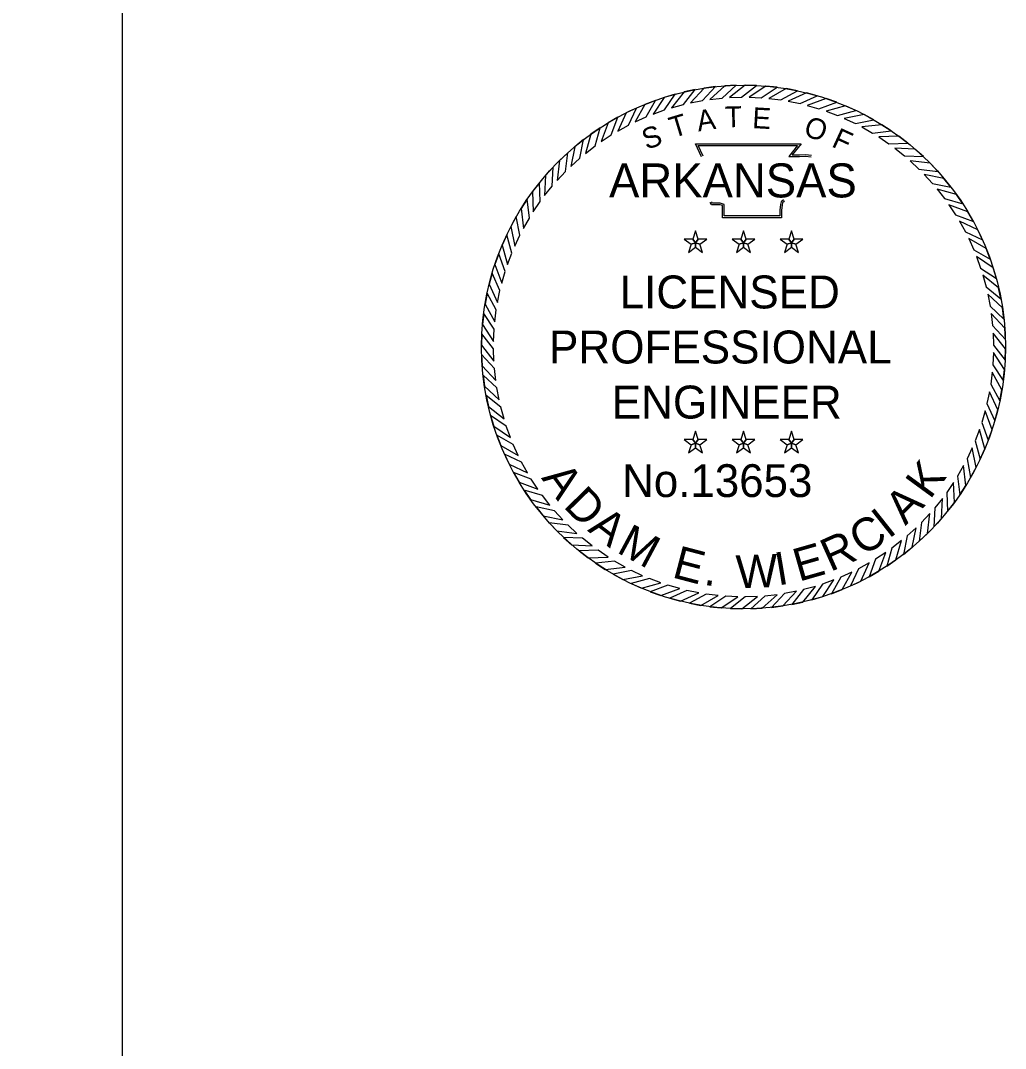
# Model space of a CAD drawing. Extents: x 0 to 38, y -1.3 to 22.5.
# Drawn here: x 33.533 to 38.045, y 10.605 to 15.315 of the extents above; entities that cross this region are included whole.
import ezdxf

# ---------------------------------------------------------------- set-up
doc = ezdxf.new("R2010")
doc.units = 0
for name, color, linetype in [('G-ANNO-STMP', 7, 'Continuous'), ('G-Border-Paper', 7, 'Continuous'), ('G-No Plot-Stamp-1', 7, 'Continuous'), ('G-No Plot-Stamp-2', 7, 'Continuous')]:
    doc.layers.add(name, color=color, linetype=linetype)

msp = doc.modelspace()

# ---------------------------------------------------------------- linework, layer by layer
at = {"layer": 'G-ANNO-STMP'}
for points in [[(36.623, 14.9987), (36.5725, 14.988), (36.5152, 14.9161), (36.569, 14.9308)], [(36.7162, 15.0124), (36.665, 15.0058), (36.6023, 14.9385), (36.657, 14.949)], [(36.8102, 15.0188), (36.7587, 15.0162), (36.6908, 14.9541), (36.7463, 14.9602)], [(36.9044, 15.0178), (36.8528, 15.0192), (36.7804, 14.9626), (36.8361, 14.9644)], [(36.9983, 15.0094), (36.947, 15.0149), (36.8703, 14.9641), (36.926, 14.9615)], [(37.0912, 14.9936), (37.0405, 15.0032), (36.96, 14.9586), (37.0153, 14.9516)], [(37.1826, 14.9707), (37.1327, 14.9841), (37.049, 14.946), (37.1036, 14.9347)], [(36.4412, 14.9495), (36.393, 14.9311), (36.3477, 14.851), (36.3985, 14.874)], [(36.5311, 14.9776), (36.4816, 14.9631), (36.4302, 14.8868), (36.4826, 14.9057)], [(37.2719, 14.9406), (37.2233, 14.9579), (37.1368, 14.9265), (37.1904, 14.9109)], [(36.3537, 14.9143), (36.3071, 14.8922), (36.2682, 14.8089), (36.3171, 14.8357)], [(37.3585, 14.9036), (37.3114, 14.9247), (37.2228, 14.9001), (37.275, 14.8804)], [(36.2693, 14.8725), (36.2246, 14.8468), (36.1924, 14.7606), (36.239, 14.7912)], [(37.442, 14.8599), (37.3967, 14.8847), (37.3064, 14.8671), (37.3569, 14.8434)], [(37.5218, 14.8098), (37.4786, 14.8381), (37.3872, 14.8276), (37.4357, 14.8)], [(36.1885, 14.8241), (36.1459, 14.795), (36.1205, 14.7065), (36.1646, 14.7407)], [(36.1116, 14.7695), (36.0715, 14.7371), (36.0531, 14.647), (36.0944, 14.6845)], [(37.5975, 14.7536), (37.5566, 14.7852), (37.4647, 14.7819), (37.5108, 14.7506)], [(36.0393, 14.7091), (36.0018, 14.6737), (35.9906, 14.5824), (36.0288, 14.623)], [(37.6685, 14.6917), (37.6302, 14.7263), (37.5383, 14.7303), (37.5818, 14.6955)], [(37.7344, 14.6243), (37.699, 14.6619), (37.6077, 14.6731), (37.6483, 14.6349)], [(35.972, 14.6432), (35.9374, 14.6049), (35.9334, 14.513), (35.9682, 14.5565)], [(37.7948, 14.552), (37.7624, 14.5922), (37.6723, 14.6106), (37.7098, 14.5693)], [(35.91, 14.5722), (35.8785, 14.5313), (35.8817, 14.4394), (35.9131, 14.4855)], [(37.8494, 14.4752), (37.8203, 14.5178), (37.7318, 14.5432), (37.766, 14.4991)], [(35.8538, 14.4966), (35.8256, 14.4533), (35.8361, 14.3619), (35.8637, 14.4104)], [(37.8978, 14.3944), (37.8721, 14.4391), (37.7859, 14.4713), (37.8165, 14.4247)], [(35.8038, 14.4167), (35.779, 14.3714), (35.7966, 14.2811), (35.8203, 14.3316)], [(37.9396, 14.3099), (37.9175, 14.3566), (37.8342, 14.3955), (37.861, 14.3466)], [(35.7601, 14.3332), (35.739, 14.2861), (35.7636, 14.1975), (35.7833, 14.2497)], [(36.6251, 14.2971), (36.6374, 14.314), (36.6251, 14.3519), (36.6127, 14.314)], [(36.8445, 14.2971), (36.8568, 14.314), (36.8445, 14.3519), (36.8322, 14.314)], [(37.0639, 14.2971), (37.0763, 14.314), (37.0639, 14.3519), (37.0516, 14.314)], [(36.6251, 14.2971), (36.6127, 14.314), (36.5729, 14.314), (36.6051, 14.2906)], [(36.6251, 14.2971), (36.6051, 14.2906), (36.5928, 14.2527), (36.6251, 14.2761)], [(36.6251, 14.2971), (36.645, 14.2906), (36.6772, 14.314), (36.6374, 14.314)], [(36.6251, 14.2971), (36.6251, 14.2761), (36.6573, 14.2527), (36.645, 14.2906)], [(36.8445, 14.2971), (36.8322, 14.314), (36.7923, 14.314), (36.8246, 14.2906)], [(36.8445, 14.2971), (36.8246, 14.2906), (36.8122, 14.2527), (36.8445, 14.2761)], [(36.8445, 14.2971), (36.8644, 14.2906), (36.8967, 14.314), (36.8568, 14.314)], [(36.8445, 14.2971), (36.8445, 14.2761), (36.8767, 14.2527), (36.8644, 14.2906)], [(37.0639, 14.2971), (37.0516, 14.314), (37.0118, 14.314), (37.044, 14.2906)], [(37.0639, 14.2971), (37.044, 14.2906), (37.0317, 14.2527), (37.0639, 14.2761)], [(37.0639, 14.2971), (37.0839, 14.2906), (37.1161, 14.314), (37.0763, 14.314)], [(37.0639, 14.2971), (37.0639, 14.2761), (37.0962, 14.2527), (37.0839, 14.2906)], [(37.9748, 14.2225), (37.9564, 14.2707), (37.8763, 14.316), (37.8993, 14.2652)], [(35.7231, 14.2466), (35.7058, 14.198), (35.7372, 14.1115), (35.7528, 14.1651)], [(38.0029, 14.1326), (37.9884, 14.1821), (37.9121, 14.2335), (37.931, 14.1811)], [(35.693, 14.1573), (35.6796, 14.1075), (35.7177, 14.0238), (35.729, 14.0784)], [(38.0239, 14.0407), (38.0133, 14.0912), (37.9413, 14.1485), (37.9561, 14.0947)], [(35.67, 14.0659), (35.6605, 14.0152), (35.7051, 13.9347), (35.7121, 13.99)], [(38.0377, 13.9475), (38.0311, 13.9987), (37.9638, 14.0614), (37.9743, 14.0067)], [(35.6543, 13.973), (35.6488, 13.9217), (35.6996, 13.845), (35.7022, 13.9007)], [(38.0441, 13.8535), (38.0415, 13.905), (37.9794, 13.9729), (37.9855, 13.9174)], [(35.6459, 13.8791), (35.6444, 13.8275), (35.7011, 13.7551), (35.6993, 13.8108)], [(38.0431, 13.7593), (38.0445, 13.8109), (37.9879, 13.8833), (37.9897, 13.8276)], [(35.6449, 13.7849), (35.6475, 13.7334), (35.7096, 13.6655), (35.7035, 13.721)], [(38.0347, 13.6654), (38.0402, 13.7167), (37.9894, 13.7934), (37.9868, 13.7377)], [(35.6513, 13.6909), (35.6579, 13.6397), (35.7252, 13.577), (35.7147, 13.6317)], [(38.0189, 13.5725), (38.0285, 13.6232), (37.9839, 13.7037), (37.9769, 13.6484)], [(37.996, 13.4811), (38.0094, 13.5309), (37.9713, 13.6146), (37.96, 13.56)], [(35.665, 13.5977), (35.6757, 13.5472), (35.7476, 13.4899), (35.7329, 13.5437)], [(37.9659, 13.3918), (37.9832, 13.4404), (37.9518, 13.5269), (37.9362, 13.4733)], [(35.6861, 13.5058), (35.7006, 13.4563), (35.7769, 13.4049), (35.758, 13.4573)], [(36.6251, 13.3782), (36.6374, 13.3951), (36.6251, 13.433), (36.6127, 13.3951)], [(36.8445, 13.3782), (36.8568, 13.3951), (36.8445, 13.433), (36.8322, 13.3951)], [(37.0639, 13.3782), (37.0763, 13.3951), (37.0639, 13.433), (37.0516, 13.3951)], [(37.9289, 13.3052), (37.95, 13.3523), (37.9254, 13.4409), (37.9057, 13.3887)], [(35.7142, 13.4159), (35.7326, 13.3677), (35.8127, 13.3224), (35.7897, 13.3732)], [(36.6251, 13.3782), (36.6127, 13.3951), (36.5729, 13.3951), (36.6051, 13.3717)], [(36.6251, 13.3782), (36.6051, 13.3717), (36.5928, 13.3338), (36.6251, 13.3572)], [(36.6251, 13.3782), (36.645, 13.3717), (36.6772, 13.3951), (36.6374, 13.3951)], [(36.6251, 13.3782), (36.6251, 13.3572), (36.6573, 13.3338), (36.645, 13.3717)], [(36.8445, 13.3782), (36.8322, 13.3951), (36.7923, 13.3951), (36.8246, 13.3717)], [(36.8445, 13.3782), (36.8246, 13.3717), (36.8122, 13.3338), (36.8445, 13.3572)], [(36.8445, 13.3782), (36.8644, 13.3717), (36.8967, 13.3951), (36.8568, 13.3951)], [(36.8445, 13.3782), (36.8445, 13.3572), (36.8767, 13.3338), (36.8644, 13.3717)], [(37.0639, 13.3782), (37.0516, 13.3951), (37.0118, 13.3951), (37.044, 13.3717)], [(37.0639, 13.3782), (37.044, 13.3717), (37.0317, 13.3338), (37.0639, 13.3572)], [(37.0639, 13.3782), (37.0839, 13.3717), (37.1161, 13.3951), (37.0763, 13.3951)], [(37.0639, 13.3782), (37.0639, 13.3572), (37.0962, 13.3338), (37.0839, 13.3717)], [(37.8852, 13.2217), (37.91, 13.267), (37.8924, 13.3573), (37.8687, 13.3068)], [(35.7493, 13.3285), (35.7715, 13.2818), (35.8548, 13.2429), (35.8279, 13.2918)], [(35.7912, 13.244), (35.8169, 13.1993), (35.9031, 13.1671), (35.8725, 13.2137)], [(37.8351, 13.1418), (37.8633, 13.1851), (37.8529, 13.2765), (37.8253, 13.228)], [(37.7789, 13.0662), (37.8105, 13.1071), (37.8072, 13.199), (37.7759, 13.1529)], [(35.8396, 13.1632), (35.8687, 13.1206), (35.9572, 13.0952), (35.923, 13.1393)], [(37.717, 12.9952), (37.7516, 13.0335), (37.7556, 13.1254), (37.7208, 13.0819)], [(35.8942, 13.0864), (35.9266, 13.0462), (36.0167, 13.0278), (35.9792, 13.0691)], [(37.6496, 12.9293), (37.6872, 12.9647), (37.6984, 13.056), (37.6602, 13.0154)], [(35.9546, 13.0141), (35.99, 12.9765), (36.0813, 12.9653), (36.0407, 13.0035)], [(37.5773, 12.8689), (37.6175, 12.9013), (37.6359, 12.9914), (37.5946, 12.9539)], [(36.0205, 12.9467), (36.0588, 12.9121), (36.1507, 12.9081), (36.1072, 12.9429)], [(37.5005, 12.8143), (37.5431, 12.8434), (37.5685, 12.9319), (37.5244, 12.8977)], [(36.0915, 12.8848), (36.1324, 12.8532), (36.2243, 12.8565), (36.1782, 12.8878)], [(37.4197, 12.7659), (37.4644, 12.7916), (37.4966, 12.8778), (37.45, 12.8472)], [(36.1671, 12.8286), (36.2104, 12.8003), (36.3018, 12.8108), (36.2533, 12.8384)], [(37.3352, 12.7241), (37.3819, 12.7462), (37.4207, 12.8295), (37.3719, 12.8027)], [(36.247, 12.7785), (36.2923, 12.7537), (36.3825, 12.7713), (36.3321, 12.795)], [(37.2478, 12.6889), (37.296, 12.7073), (37.3413, 12.7874), (37.2905, 12.7644)], [(36.3305, 12.7348), (36.3776, 12.7137), (36.4662, 12.7383), (36.414, 12.758)], [(36.4171, 12.6978), (36.4657, 12.6805), (36.5522, 12.7119), (36.4986, 12.7275)], [(37.066, 12.6397), (37.1165, 12.6504), (37.1738, 12.7223), (37.12, 12.7076)], [(37.1579, 12.6608), (37.2074, 12.6753), (37.2588, 12.7516), (37.2064, 12.7327)], [(36.5064, 12.6677), (36.5562, 12.6543), (36.6399, 12.6924), (36.5853, 12.7037)], [(36.5978, 12.6448), (36.6485, 12.6352), (36.729, 12.6798), (36.6737, 12.6868)], [(36.6907, 12.629), (36.742, 12.6235), (36.8187, 12.6743), (36.763, 12.6769)], [(36.7846, 12.6206), (36.8362, 12.6192), (36.9086, 12.6758), (36.8529, 12.674)], [(36.8788, 12.6196), (36.9303, 12.6222), (36.9982, 12.6843), (36.9427, 12.6782)], [(36.9728, 12.626), (37.024, 12.6326), (37.0867, 12.6999), (37.032, 12.6894)]]:
    msp.add_lwpolyline(points, close=True, dxfattribs=at)
for points in [[(36.6522, 14.6902), (36.6243, 14.7508), (37.1083, 14.7511), (37.0679, 14.7003), (37.1007, 14.7007), (37.1282, 14.701), (37.1557, 14.698)], [(36.6592, 14.6934), (36.6362, 14.7431), (37.0924, 14.7434), (37.0518, 14.6924), (37.1008, 14.693), (37.1279, 14.6934), (37.1548, 14.6904)], [(37.032, 14.4873), (37.0238, 14.4806), (37.021, 14.4706), (37.0183, 14.4455), (37.0183, 14.412), (36.7481, 14.412), (36.7481, 14.4572), (36.7481, 14.4672), (36.7371, 14.4706), (36.6987, 14.4706), (36.6919, 14.481)], [(37.0272, 14.4933), (37.017, 14.485), (37.0135, 14.472), (37.0106, 14.4459), (37.0106, 14.4197), (36.7558, 14.4197), (36.7558, 14.4572), (36.7558, 14.4729), (36.7383, 14.4783), (36.7028, 14.4783), (36.6983, 14.4852)]]:
    msp.add_lwpolyline(points, dxfattribs=at)
at = {"layer": 'G-Border-Paper'}
msp.add_lwpolyline([(34, 22), (0, 22), (0, 0), (34, 0)], close=True, dxfattribs=at)
at = {"layer": 'G-No Plot-Stamp-1'}
msp.add_circle((36.8445, 13.8192), 1.2, dxfattribs=at)
at = {"layer": 'G-No Plot-Stamp-2'}
msp.add_circle((36.8445, 13.8192), 1.2, dxfattribs=at)

# ---------------------------------------------------------------- texts
at = {"layer": 'G-ANNO-STMP'}
for s, height, rotation, p in [('T', 0.0955, 16.9015, (36.5215, 14.7765)), ('A', 0.0955, 8.6788, (36.6375, 14.8067)), ('T', 0.0955, 1.4789, (36.7608, 14.8257)), ('E', 0.0955, 356.672, (36.883, 14.8228)), ('O', 0.0955, 341.2218, (37.1148, 14.7901)), ('S', 0.0955, 19.7726, (36.4001, 14.7219)), ('F', 0.0955, 335.3628, (37.2435, 14.7398)), ('K', 0.1509, 53.8471, (37.6991, 13.1171)), ('A', 0.1509, 305.982, (35.916, 13.2186)), ('D', 0.1509, 314.3022, (36.015, 13.0882)), ('A', 0.1509, 45.185, (37.5859, 12.9987)), ('A', 0.1509, 322.6223, (36.1269, 12.9778)), ('I', 0.1509, 38.4057, (37.5097, 12.9375)), ('M', 0.1509, 331.7969, (36.2586, 12.8804)), ('C', 0.1509, 32.1396, (37.39, 12.8578)), ('R', 0.1509, 24.1616, (37.2422, 12.7874)), ('E', 0.1509, 16.0125, (37.0983, 12.7432)), ('E', 0.1509, 345.2782, (36.5127, 12.7647)), ('W', 0.1509, 2.1127, (36.8126, 12.7131)), ('I', 0.1509, 9.5753, (37.0021, 12.726)), ('.', 0.1509, 350.8583, (36.6593, 12.7306))]:
    msp.add_text(s, height=height, rotation=rotation, dxfattribs=at).set_placement(p)
for s, height, p in [('ARKANSAS', 0.15584, (36.2286, 14.5048)), ('LICENSED', 0.15087, (36.2769, 13.9961)), ('PROFESSIONAL', 0.150867, (35.9537, 13.7438)), ('ENGINEER', 0.15087, (36.241, 13.4915)), ('No.13653', 0.15027, (36.2886, 13.1318))]:
    msp.add_text(s, height=height, dxfattribs=at).set_placement(p)

doc.saveas('drawing.dxf')
